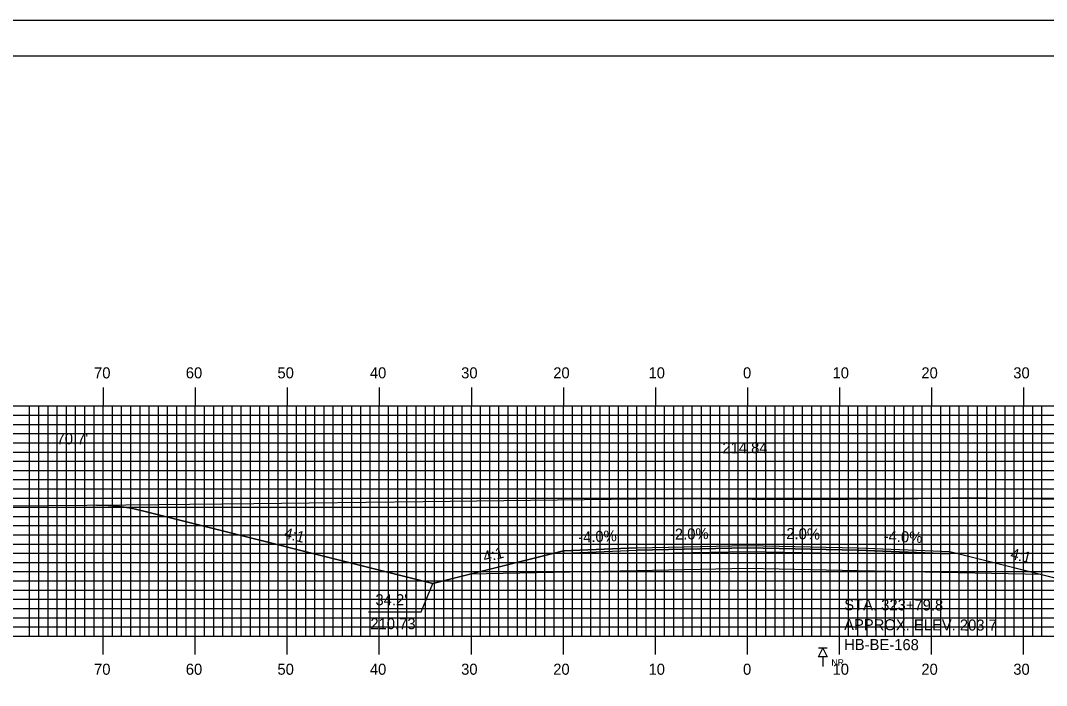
# Model space of a CAD drawing. Extents: x 1820818 to 1821161, y 442591 to 442811.
# Drawn here: x 1820904.7 to 1821016.2, y 442738.3 to 442810.5 of the extents above; entities that cross this region are included whole.
import ezdxf

# ---------------------------------------------------------------- set-up
doc = ezdxf.new("R2010")
doc.units = 0
for name, color, linetype in [('ANNOTATION', 7, 'Continuous'), ('BORDER', 7, 'Continuous'), ('BORING - NO REFUSAL', 7, 'Continuous'), ('D_Roadway_Centerline', 7, 'Continuous'), ('D_Roadway_Centerline_Text', 7, 'Continuous'), ('D_Roadway_Edge_Shoulder', 7, 'Continuous'), ('D_Roadway_Edge_TW', 7, 'Continuous'), ('D_Roadway_Pavement', 7, 'Continuous'), ('D_Roadway_SlopeLines', 7, 'Continuous'), ('D_Roadway_SubGrade', 7, 'Continuous'), ('D_Text_Standard', 7, 'Continuous'), ('H_V ANNOTATION', 7, 'Continuous'), ('MAJOR', 7, 'Continuous'), ('MINOR', 7, 'Continuous'), ('PLOT BOUNDARY', 7, 'Continuous'), ('S_Roadway_Centerline', 7, 'Continuous')]:
    doc.layers.add(name, color=color, linetype=linetype)

msp = doc.modelspace()

# ---------------------------------------------------------------- linework, layer by layer
at = {"layer": 'ANNOTATION'}
msp.add_lwpolyline([(1820942.56, 442746.29), (1820948.25, 442746.29), (1820949.54, 442749.4)], dxfattribs=at)
at = {"layer": 'BORDER'}
msp.add_lwpolyline([(1820834.12, 442596.67), (1821154.12, 442596.67), (1821154.12, 442806.67), (1820834.12, 442806.67)], close=True, dxfattribs=at)
at = {"layer": 'BORING - NO REFUSAL'}
for p, q in [((1820992.4, 442742.37), (1820991.44, 442742.37)), ((1820991.92, 442741.41), (1820991.92, 442740.35))]:
    msp.add_line(p, q, dxfattribs=at)
msp.add_lwpolyline([(1820991.92, 442742.37), (1820992.4, 442741.41), (1820991.44, 442741.41)], close=True, dxfattribs=at)
at = {"layer": 'D_Roadway_Centerline'}
msp.add_lwpolyline([(1820912.99, 442757.89), (1820914.24, 442757.86), (1820915.49, 442757.75), (1820916.74, 442757.56), (1820917.99, 442757.29), (1820949.54, 442749.4), (1820953.54, 442750.4), (1820963.72, 442752.94), (1820971.72, 442753.26), (1820983.72, 442753.5), (1820995.72, 442753.26), (1821005.72, 442752.86), (1821015.72, 442750.36), (1821019.72, 442749.36), (1821054.89, 442758.15), (1821056.14, 442758.43), (1821057.39, 442758.63), (1821058.64, 442758.75), (1821059.89, 442758.8)], dxfattribs=at)
at = {"layer": 'D_Roadway_Edge_Shoulder'}
for points in [[(1820971.72, 442753.26), (1820963.72, 442752.94), (1820963.72, 442752.69), (1820971.72, 442753.01)], [(1820995.72, 442753.26), (1821005.72, 442752.86), (1821005.72, 442752.61), (1820995.72, 442753.01)]]:
    msp.add_lwpolyline(points, close=True, dxfattribs=at)
at = {"layer": 'D_Roadway_Edge_TW'}
msp.add_lwpolyline([(1820971.72, 442753.01), (1820971.72, 442753.26), (1820983.72, 442753.5), (1820995.72, 442753.26), (1820995.72, 442753.01), (1820983.72, 442753.25)], close=True, dxfattribs=at)
at = {"layer": 'D_Roadway_Pavement'}
msp.add_lwpolyline([(1820971.72, 442752.59), (1820971.72, 442753.01), (1820983.72, 442753.25), (1820995.72, 442753.01), (1820995.72, 442752.59), (1820983.72, 442752.83)], close=True, dxfattribs=at)
at = {"layer": 'D_Roadway_SlopeLines'}
for points in [[(1820949.54, 442749.4), (1820917.99, 442757.29), (1820916.74, 442757.56), (1820915.49, 442757.75), (1820914.24, 442757.86), (1820912.99, 442757.89)], [(1820963.72, 442752.94), (1820949.54, 442749.4)], [(1821005.72, 442752.86), (1821019.72, 442749.36)]]:
    msp.add_lwpolyline(points, dxfattribs=at)
at = {"layer": 'D_Roadway_SubGrade'}
msp.add_lwpolyline([(1820971.72, 442750.76), (1820953.54, 442750.4), (1820963.72, 442752.94), (1820963.72, 442752.69), (1820971.72, 442753.01), (1820983.72, 442753.25), (1820995.72, 442753.01), (1821005.72, 442752.61), (1821005.72, 442752.86), (1821015.72, 442750.36), (1820995.72, 442750.76), (1820983.72, 442751)], close=True, dxfattribs=at)
at = {"layer": 'MAJOR'}
for p, q in [((1820913.72, 442770.67), (1820913.72, 442768.67)), ((1820923.72, 442770.67), (1820923.72, 442768.67)), ((1820933.72, 442770.67), (1820933.72, 442768.67)), ((1820943.72, 442770.67), (1820943.72, 442768.67)), ((1820953.72, 442770.67), (1820953.72, 442768.67)), ((1820963.72, 442770.67), (1820963.72, 442768.67)), ((1820973.72, 442770.67), (1820973.72, 442768.67)), ((1820983.72, 442770.67), (1820983.72, 442768.67)), ((1820993.72, 442770.67), (1820993.72, 442768.67)), ((1821003.72, 442770.67), (1821003.72, 442768.67)), ((1821013.72, 442770.67), (1821013.72, 442768.67)), ((1820843.72, 442768.67), (1821123.72, 442768.67)), ((1820843.72, 442768.67), (1821123.72, 442768.67)), ((1820913.72, 442743.67), (1820913.72, 442768.67)), ((1820923.72, 442743.67), (1820923.72, 442768.67)), ((1820933.72, 442743.67), (1820933.72, 442768.67)), ((1820943.72, 442743.67), (1820943.72, 442768.67)), ((1820953.72, 442743.67), (1820953.72, 442768.67)), ((1820963.72, 442743.67), (1820963.72, 442768.67)), ((1820973.72, 442743.67), (1820973.72, 442768.67)), ((1820983.72, 442743.67), (1820983.72, 442768.67)), ((1820993.72, 442743.67), (1820993.72, 442768.67)), ((1821003.72, 442743.67), (1821003.72, 442768.67)), ((1821013.72, 442743.67), (1821013.72, 442768.67)), ((1820843.72, 442763.67), (1821123.72, 442763.67)), ((1820843.72, 442758.67), (1821123.72, 442758.67)), ((1820843.72, 442753.67), (1821123.72, 442753.67)), ((1820843.72, 442748.67), (1821123.72, 442748.67)), ((1820843.72, 442743.67), (1821123.72, 442743.67)), ((1820843.72, 442743.67), (1821123.72, 442743.67)), ((1820913.72, 442741.66), (1820913.72, 442743.67)), ((1820923.72, 442741.66), (1820923.72, 442743.67)), ((1820933.72, 442741.66), (1820933.72, 442743.67)), ((1820943.72, 442741.66), (1820943.72, 442743.67)), ((1820953.72, 442741.66), (1820953.72, 442743.67)), ((1820963.72, 442741.66), (1820963.72, 442743.67)), ((1820973.72, 442741.66), (1820973.72, 442743.67)), ((1820983.72, 442741.66), (1820983.72, 442743.67)), ((1820993.72, 442741.66), (1820993.72, 442743.67)), ((1821003.72, 442741.66), (1821003.72, 442743.67)), ((1821013.72, 442741.66), (1821013.72, 442743.67))]:
    msp.add_line(p, q, dxfattribs=at)
at = {"layer": 'MINOR'}
for p, q in [((1820905.72, 442743.67), (1820905.72, 442768.67)), ((1820906.72, 442743.67), (1820906.72, 442768.67)), ((1820907.72, 442743.67), (1820907.72, 442768.67)), ((1820908.72, 442743.67), (1820908.72, 442768.67)), ((1820909.72, 442743.67), (1820909.72, 442768.67)), ((1820910.72, 442743.67), (1820910.72, 442768.67)), ((1820911.72, 442743.67), (1820911.72, 442768.67)), ((1820912.72, 442743.67), (1820912.72, 442768.67)), ((1820914.72, 442743.67), (1820914.72, 442768.67)), ((1820915.72, 442743.67), (1820915.72, 442768.67)), ((1820916.72, 442743.67), (1820916.72, 442768.67)), ((1820917.72, 442743.67), (1820917.72, 442768.67)), ((1820918.72, 442743.67), (1820918.72, 442768.67)), ((1820919.72, 442743.67), (1820919.72, 442768.67)), ((1820920.72, 442743.67), (1820920.72, 442768.67)), ((1820921.72, 442743.67), (1820921.72, 442768.67)), ((1820922.72, 442743.67), (1820922.72, 442768.67)), ((1820924.72, 442743.67), (1820924.72, 442768.67)), ((1820925.72, 442743.67), (1820925.72, 442768.67)), ((1820926.72, 442743.67), (1820926.72, 442768.67)), ((1820927.72, 442743.67), (1820927.72, 442768.67)), ((1820928.72, 442743.67), (1820928.72, 442768.67)), ((1820929.72, 442743.67), (1820929.72, 442768.67)), ((1820930.72, 442743.67), (1820930.72, 442768.67)), ((1820931.72, 442743.67), (1820931.72, 442768.67)), ((1820932.72, 442743.67), (1820932.72, 442768.67)), ((1820934.72, 442743.67), (1820934.72, 442768.67)), ((1820935.72, 442743.67), (1820935.72, 442768.67)), ((1820936.72, 442743.67), (1820936.72, 442768.67)), ((1820937.72, 442743.67), (1820937.72, 442768.67)), ((1820938.72, 442743.67), (1820938.72, 442768.67)), ((1820939.72, 442743.67), (1820939.72, 442768.67)), ((1820940.72, 442743.67), (1820940.72, 442768.67)), ((1820941.72, 442743.67), (1820941.72, 442768.67)), ((1820942.72, 442743.67), (1820942.72, 442768.67)), ((1820944.72, 442743.67), (1820944.72, 442768.67)), ((1820945.72, 442743.67), (1820945.72, 442768.67)), ((1820946.72, 442743.67), (1820946.72, 442768.67)), ((1820947.72, 442743.67), (1820947.72, 442768.67)), ((1820948.72, 442743.67), (1820948.72, 442768.67)), ((1820949.72, 442743.67), (1820949.72, 442768.67)), ((1820950.72, 442743.67), (1820950.72, 442768.67)), ((1820951.72, 442743.67), (1820951.72, 442768.67)), ((1820952.72, 442743.67), (1820952.72, 442768.67)), ((1820954.72, 442743.67), (1820954.72, 442768.67)), ((1820955.72, 442743.67), (1820955.72, 442768.67)), ((1820956.72, 442743.67), (1820956.72, 442768.67)), ((1820957.72, 442743.67), (1820957.72, 442768.67)), ((1820958.72, 442743.67), (1820958.72, 442768.67)), ((1820959.72, 442743.67), (1820959.72, 442768.67)), ((1820960.72, 442743.67), (1820960.72, 442768.67)), ((1820961.72, 442743.67), (1820961.72, 442768.67)), ((1820962.72, 442743.67), (1820962.72, 442768.67)), ((1820964.72, 442743.67), (1820964.72, 442768.67)), ((1820965.72, 442743.67), (1820965.72, 442768.67)), ((1820966.72, 442743.67), (1820966.72, 442768.67)), ((1820967.72, 442743.67), (1820967.72, 442768.67)), ((1820968.72, 442743.67), (1820968.72, 442768.67)), ((1820969.72, 442743.67), (1820969.72, 442768.67)), ((1820970.72, 442743.67), (1820970.72, 442768.67)), ((1820971.72, 442743.67), (1820971.72, 442768.67)), ((1820972.72, 442743.67), (1820972.72, 442768.67)), ((1820974.72, 442743.67), (1820974.72, 442768.67)), ((1820975.72, 442743.67), (1820975.72, 442768.67)), ((1820976.72, 442743.67), (1820976.72, 442768.67)), ((1820977.72, 442743.67), (1820977.72, 442768.67)), ((1820978.72, 442743.67), (1820978.72, 442768.67)), ((1820979.72, 442743.67), (1820979.72, 442768.67)), ((1820980.72, 442743.67), (1820980.72, 442768.67)), ((1820981.72, 442743.67), (1820981.72, 442768.67)), ((1820982.72, 442743.67), (1820982.72, 442768.67)), ((1820984.72, 442743.67), (1820984.72, 442768.67)), ((1820985.72, 442743.67), (1820985.72, 442768.67)), ((1820986.72, 442743.67), (1820986.72, 442768.67)), ((1820987.72, 442743.67), (1820987.72, 442768.67)), ((1820988.72, 442743.67), (1820988.72, 442768.67)), ((1820989.72, 442743.67), (1820989.72, 442768.67)), ((1820990.72, 442743.67), (1820990.72, 442768.67)), ((1820991.72, 442743.67), (1820991.72, 442768.67)), ((1820992.72, 442743.67), (1820992.72, 442768.67)), ((1820994.72, 442743.67), (1820994.72, 442768.67)), ((1820995.72, 442743.67), (1820995.72, 442768.67)), ((1820996.72, 442743.67), (1820996.72, 442768.67)), ((1820997.72, 442743.67), (1820997.72, 442768.67)), ((1820998.72, 442743.67), (1820998.72, 442768.67)), ((1820999.72, 442743.67), (1820999.72, 442768.67)), ((1821000.72, 442743.67), (1821000.72, 442768.67)), ((1821001.72, 442743.67), (1821001.72, 442768.67)), ((1821002.72, 442743.67), (1821002.72, 442768.67)), ((1821004.72, 442743.67), (1821004.72, 442768.67)), ((1821005.72, 442743.67), (1821005.72, 442768.67)), ((1821006.72, 442743.67), (1821006.72, 442768.67)), ((1821007.72, 442743.67), (1821007.72, 442768.67)), ((1821008.72, 442743.67), (1821008.72, 442768.67)), ((1821009.72, 442743.67), (1821009.72, 442768.67)), ((1821010.72, 442743.67), (1821010.72, 442768.67)), ((1821011.72, 442743.67), (1821011.72, 442768.67)), ((1821012.72, 442743.67), (1821012.72, 442768.67)), ((1821014.72, 442743.67), (1821014.72, 442768.67)), ((1821015.72, 442743.67), (1821015.72, 442768.67)), ((1820843.72, 442767.67), (1821123.72, 442767.67)), ((1820843.72, 442766.67), (1821123.72, 442766.67)), ((1820843.72, 442765.67), (1821123.72, 442765.67)), ((1820843.72, 442764.67), (1821123.72, 442764.67)), ((1820843.72, 442762.67), (1821123.72, 442762.67)), ((1820843.72, 442761.67), (1821123.72, 442761.67)), ((1820843.72, 442760.67), (1821123.72, 442760.67)), ((1820843.72, 442759.67), (1821123.72, 442759.67)), ((1820843.72, 442757.67), (1821123.72, 442757.67)), ((1820843.72, 442756.67), (1821123.72, 442756.67)), ((1820843.72, 442755.67), (1821123.72, 442755.67)), ((1820843.72, 442754.67), (1821123.72, 442754.67)), ((1820843.72, 442752.67), (1821123.72, 442752.67)), ((1820843.72, 442751.67), (1821123.72, 442751.67)), ((1820843.72, 442750.67), (1821123.72, 442750.67)), ((1820843.72, 442749.67), (1821123.72, 442749.67)), ((1820843.72, 442747.67), (1821123.72, 442747.67)), ((1820843.72, 442746.67), (1821123.72, 442746.67)), ((1820843.72, 442745.67), (1821123.72, 442745.67)), ((1820843.72, 442744.67), (1821123.72, 442744.67))]:
    msp.add_line(p, q, dxfattribs=at)
at = {"layer": 'PLOT BOUNDARY'}
msp.add_lwpolyline([(1820817.93, 442590.55), (1821157.93, 442590.55), (1821157.93, 442810.55), (1820817.93, 442810.55)], close=True, dxfattribs=at)
at = {"layer": 'S_Roadway_Centerline'}
msp.add_lwpolyline([(1820843.72, 442757.45), (1820846.18, 442757.4), (1820848.12, 442757.43), (1820851.86, 442757.38), (1820865.22, 442757.44), (1820874.34, 442757.53), (1820886.36, 442757.69), (1820916.16, 442757.92), (1820930.08, 442758.08), (1820936.08, 442758.16), (1820948.48, 442758.31), (1820974.76, 442758.61), (1820988.97, 442758.52), (1821000.35, 442758.6), (1821007.84, 442758.74), (1821017.58, 442758.53)], dxfattribs=at)

# ---------------------------------------------------------------- texts
at = {"layer": 'ANNOTATION'}
for s, rotation, p in [('4:1', 345.9638, (1820933.27, 442754.33)), ('-4.0%', 2.2906, (1820965.35, 442753.81)), ('-2.0%', 1.1458, (1820975.32, 442754.13)), ('-2.0%', 358.8542, (1820987.4, 442754.23)), ('-4.0%', 357.7094, (1820998.51, 442753.95)), ('4:1', 14.0362, (1820955.17, 442751.67)), ('4:1', 345.9638, (1821012.22, 442752.1))]:
    msp.add_text(s, height=1.2, rotation=rotation, dxfattribs=at).set_placement(p)
for s, p in [("34.2'", (1820943.3, 442747.02)), ('210.73', (1820942.75, 442744.42))]:
    msp.add_text(s, height=1.2, dxfattribs=at).set_placement(p)
at = {"layer": 'BORING - NO REFUSAL'}
for s, p in [('STA. 323+79.8', (1820994.24, 442746.48)), ('APPROX. ELEV. 203.7', (1820994.23, 442744.32)), ('HB-BE-168', (1820994.23, 442742.16))]:
    msp.add_text(s, height=1.2, rotation=359.8142, dxfattribs=at).set_placement(p)
msp.add_text('NR', height=0.7, dxfattribs=at).set_placement((1820992.85, 442740.45))
at = {"layer": 'D_Roadway_Centerline'}
for s, p in [('C', (1820983.71, 442753.5)), ('L', (1820983.72, 442753.49))]:
    msp.add_text(s, height=0.0146, dxfattribs=at).set_placement(p)
at = {"layer": 'D_Roadway_Centerline_Text'}
msp.add_text('214.84', height=1.2, dxfattribs=at).set_placement((1820981, 442763.53))
at = {"layer": 'D_Text_Standard'}
msp.add_text("70.7'", height=1.2, dxfattribs=at).set_placement((1820908.65, 442764.51))
at = {"layer": 'H_V ANNOTATION'}
for s, p in [('70', (1820912.72, 442771.67)), ('60', (1820922.69, 442771.67)), ('50', (1820932.65, 442771.67)), ('40', (1820942.69, 442771.67)), ('30', (1820952.61, 442771.67)), ('20', (1820962.62, 442771.67)), ('10', (1820972.97, 442771.67)), ('0', (1820983.24, 442771.67)), ('10', (1820992.97, 442771.67)), ('20', (1821002.62, 442771.67)), ('30', (1821012.61, 442771.67)), ('70', (1820912.72, 442739.47)), ('60', (1820922.69, 442739.47)), ('50', (1820932.65, 442739.47)), ('40', (1820942.69, 442739.47)), ('30', (1820952.61, 442739.47)), ('20', (1820962.62, 442739.47)), ('10', (1820972.97, 442739.47)), ('0', (1820983.24, 442739.47)), ('10', (1820992.97, 442739.47)), ('20', (1821002.62, 442739.47)), ('30', (1821012.61, 442739.47))]:
    msp.add_text(s, height=1.2, dxfattribs=at).set_placement(p)

doc.saveas('drawing.dxf')
